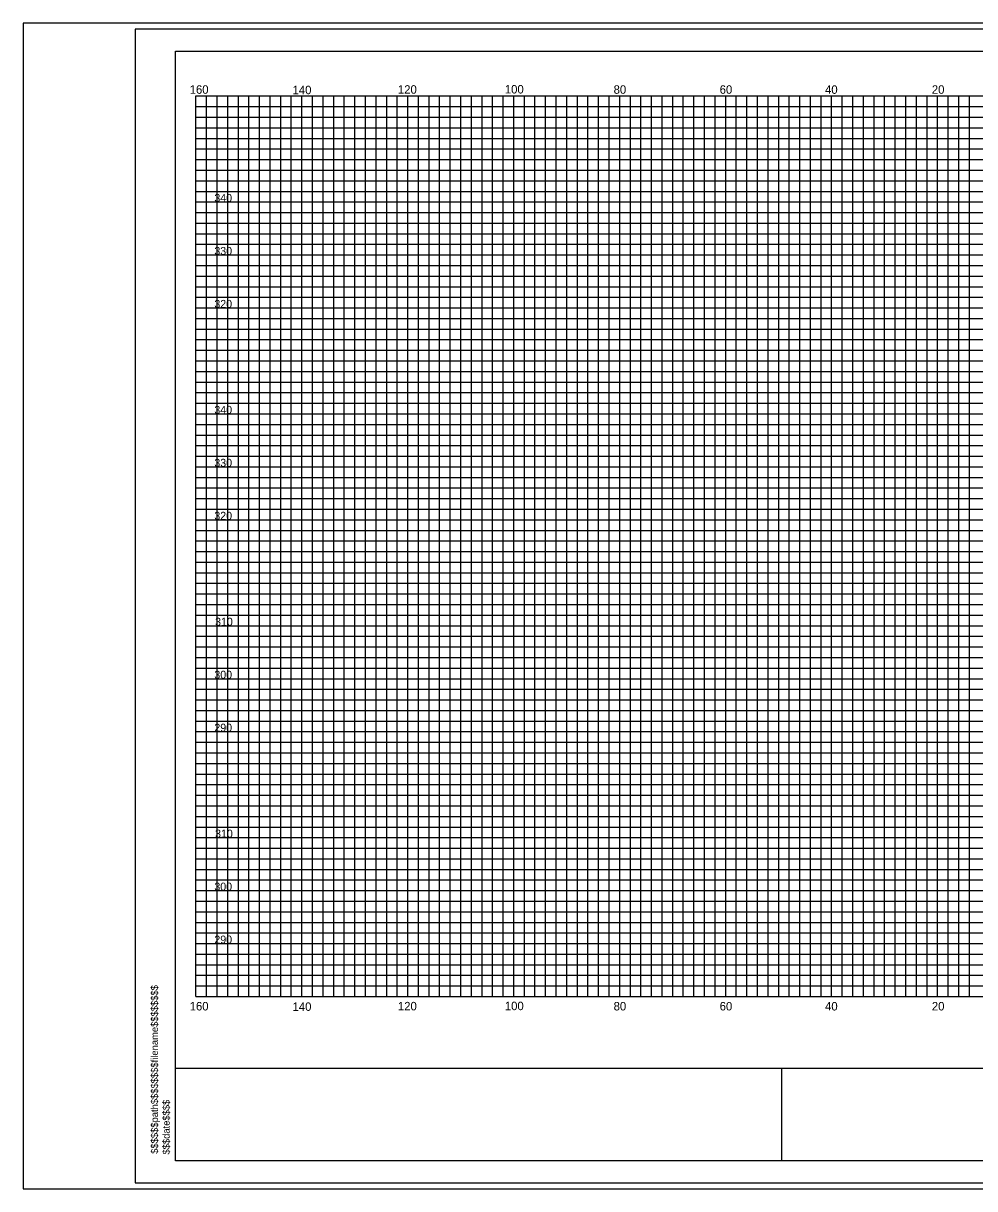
# Model space of a CAD drawing. Extents: x 967 to 1326, y 964 to 3704.
# Drawn here: x 967.4 to 1147, y 2923.7 to 3143.7 of the extents above; entities that cross this region are included whole.
import ezdxf

# ---------------------------------------------------------------- set-up
doc = ezdxf.new("R2010")
doc.units = 0
for name, color, linetype in [('Default', 7, 'Continuous'), ('RD_SHT_Bndy', 7, 'Continuous'), ('RD_SHT_IplotShp', 7, 'Continuous'), ('RD_SHT_MjGrid', 7, 'Continuous'), ('RD_SHT_MnGrid', 7, 'Continuous'), ('RD_SHT_TX', 7, 'Continuous'), ('RD_XS_TX_Station', 7, 'Continuous')]:
    doc.layers.add(name, color=color, linetype=linetype)

msp = doc.modelspace()

# ---------------------------------------------------------------- linework, layer by layer
at = {"layer": 'RD_SHT_Bndy'}
for p, q in [((996.11, 2928.98), (996.11, 3138.46)), ((996.11, 3138.46), (1323.89, 3138.46)), ((996.11, 2946.49), (1323.89, 2946.49)), ((1110.59, 2928.98), (1110.59, 2946.56)), ((1323.89, 2928.98), (996.11, 2928.98))]:
    msp.add_line(p, q, dxfattribs=at)
at = {"layer": 'RD_SHT_IplotShp'}
for points in [[(967.41, 2923.72), (1326.28, 2923.72), (1326.28, 3143.72), (967.41, 3143.72)], [(988.52, 2924.84), (1326.28, 2924.84), (1326.28, 3142.6), (988.52, 3142.6)]]:
    msp.add_lwpolyline(points, close=True, dxfattribs=at)
at = {"layer": 'RD_SHT_MjGrid'}
for p, q in [((1000, 3130), (1320, 3130)), ((1000, 2960), (1000, 3130)), ((1010, 2960), (1010, 3130)), ((1020, 2960), (1020, 3130)), ((1030, 2960), (1030, 3130)), ((1040, 2960), (1040, 3130)), ((1050, 2960), (1050, 3130)), ((1060, 2960), (1060, 3130)), ((1070, 2960), (1070, 3130)), ((1080, 2960), (1080, 3130)), ((1090, 2960), (1090, 3130)), ((1100, 2960), (1100, 3130)), ((1110, 2960), (1110, 3130)), ((1120, 2960), (1120, 3130)), ((1130, 2960), (1130, 3130)), ((1140, 2960), (1140, 3130)), ((1000, 3120), (1320, 3120)), ((1000, 3110), (1320, 3110)), ((1000, 3100), (1320, 3100)), ((1000, 3090), (1320, 3090)), ((1000, 3080), (1320, 3080)), ((1000, 3070), (1320, 3070)), ((1000, 3060), (1320, 3060)), ((1000, 3050), (1320, 3050)), ((1000, 3040), (1320, 3040)), ((1000, 3030), (1320, 3030)), ((1000, 3020), (1320, 3020)), ((1000, 3010), (1320, 3010)), ((1000, 3000), (1320, 3000)), ((1000, 2990), (1320, 2990)), ((1000, 2980), (1320, 2980)), ((1000, 2970), (1320, 2970)), ((1000, 2960), (1320, 2960))]:
    msp.add_line(p, q, dxfattribs=at)
at = {"layer": 'RD_SHT_MnGrid'}
for p, q in [((1002, 2960), (1002, 3130)), ((1004, 2960), (1004, 3130)), ((1006, 2960), (1006, 3130)), ((1008, 2960), (1008, 3130)), ((1012, 2960), (1012, 3130)), ((1014, 2960), (1014, 3130)), ((1016, 2960), (1016, 3130)), ((1018, 2960), (1018, 3130)), ((1022, 2960), (1022, 3130)), ((1024, 2960), (1024, 3130)), ((1026, 2960), (1026, 3130)), ((1028, 2960), (1028, 3130)), ((1032, 2960), (1032, 3130)), ((1034, 2960), (1034, 3130)), ((1036, 2960), (1036, 3130)), ((1038, 2960), (1038, 3130)), ((1042, 2960), (1042, 3130)), ((1044, 2960), (1044, 3130)), ((1046, 2960), (1046, 3130)), ((1048, 2960), (1048, 3130)), ((1052, 2960), (1052, 3130)), ((1054, 2960), (1054, 3130)), ((1056, 2960), (1056, 3130)), ((1058, 2960), (1058, 3130)), ((1062, 2960), (1062, 3130)), ((1064, 2960), (1064, 3130)), ((1066, 2960), (1066, 3130)), ((1068, 2960), (1068, 3130)), ((1072, 2960), (1072, 3130)), ((1074, 2960), (1074, 3130)), ((1076, 2960), (1076, 3130)), ((1078, 2960), (1078, 3130)), ((1082, 2960), (1082, 3130)), ((1084, 2960), (1084, 3130)), ((1086, 2960), (1086, 3130)), ((1088, 2960), (1088, 3130)), ((1092, 2960), (1092, 3130)), ((1094, 2960), (1094, 3130)), ((1096, 2960), (1096, 3130)), ((1098, 2960), (1098, 3130)), ((1102, 2960), (1102, 3130)), ((1104, 2960), (1104, 3130)), ((1106, 2960), (1106, 3130)), ((1108, 2960), (1108, 3130)), ((1112, 2960), (1112, 3130)), ((1114, 2960), (1114, 3130)), ((1116, 2960), (1116, 3130)), ((1118, 2960), (1118, 3130)), ((1122, 2960), (1122, 3130)), ((1124, 2960), (1124, 3130)), ((1126, 2960), (1126, 3130)), ((1128, 2960), (1128, 3130)), ((1132, 2960), (1132, 3130)), ((1134, 2960), (1134, 3130)), ((1136, 2960), (1136, 3130)), ((1138, 2960), (1138, 3130)), ((1142, 2960), (1142, 3130)), ((1144, 2960), (1144, 3130)), ((1146, 2960), (1146, 3130)), ((1000, 3128), (1320, 3128)), ((1000, 3126), (1320, 3126)), ((1000, 3124), (1320, 3124)), ((1000, 3122), (1320, 3122)), ((1000, 3118), (1320, 3118)), ((1000, 3116), (1320, 3116)), ((1000, 3114), (1320, 3114)), ((1000, 3112), (1320, 3112)), ((1000, 3108), (1320, 3108)), ((1000, 3106), (1320, 3106)), ((1000, 3104), (1320, 3104)), ((1000, 3102), (1320, 3102)), ((1000, 3098), (1320, 3098)), ((1000, 3096), (1320, 3096)), ((1000, 3094), (1320, 3094)), ((1000, 3092), (1320, 3092)), ((1000, 3088), (1320, 3088)), ((1000, 3086), (1320, 3086)), ((1000, 3084), (1320, 3084)), ((1000, 3082), (1320, 3082)), ((1000, 3078), (1320, 3078)), ((1000, 3076), (1320, 3076)), ((1000, 3074), (1320, 3074)), ((1000, 3072), (1320, 3072)), ((1000, 3068), (1320, 3068)), ((1000, 3066), (1320, 3066)), ((1000, 3064), (1320, 3064)), ((1000, 3062), (1320, 3062)), ((1000, 3058), (1320, 3058)), ((1000, 3056), (1320, 3056)), ((1000, 3054), (1320, 3054)), ((1000, 3052), (1320, 3052)), ((1000, 3048), (1320, 3048)), ((1000, 3046), (1320, 3046)), ((1000, 3044), (1320, 3044)), ((1000, 3042), (1320, 3042)), ((1000, 3038), (1320, 3038)), ((1000, 3036), (1320, 3036)), ((1000, 3034), (1320, 3034)), ((1000, 3032), (1320, 3032)), ((1000, 3028), (1320, 3028)), ((1000, 3026), (1320, 3026)), ((1000, 3024), (1320, 3024)), ((1000, 3022), (1320, 3022)), ((1000, 3018), (1320, 3018)), ((1000, 3016), (1320, 3016)), ((1000, 3014), (1320, 3014)), ((1000, 3012), (1320, 3012)), ((1000, 3008), (1320, 3008)), ((1000, 3006), (1320, 3006)), ((1000, 3004), (1320, 3004)), ((1000, 3002), (1320, 3002)), ((1000, 2998), (1320, 2998)), ((1000, 2996), (1320, 2996)), ((1000, 2994), (1320, 2994)), ((1000, 2992), (1320, 2992)), ((1000, 2988), (1320, 2988)), ((1000, 2986), (1320, 2986)), ((1000, 2984), (1320, 2984)), ((1000, 2982), (1320, 2982)), ((1000, 2978), (1320, 2978)), ((1000, 2976), (1320, 2976)), ((1000, 2974), (1320, 2974)), ((1000, 2972), (1320, 2972)), ((1000, 2968), (1320, 2968)), ((1000, 2966), (1320, 2966)), ((1000, 2964), (1320, 2964)), ((1000, 2962), (1320, 2962))]:
    msp.add_line(p, q, dxfattribs=at)
at = {"layer": 'RD_XS_TX_Station'}
msp.add_lwpolyline([(967.41, 2923.72), (1326.28, 2923.72), (1326.28, 3143.72), (967.41, 3143.72)], close=True, dxfattribs=at)

# ---------------------------------------------------------------- texts
at = {"layer": 'Default'}
for s, p in [('340', (1003.47, 3110)), ('330', (1003.47, 3100)), ('320', (1003.47, 3090)), ('340', (1003.47, 3070)), ('330', (1003.47, 3060)), ('320', (1003.47, 3050)), ('310', (1003.61, 3030)), ('300', (1003.47, 3020)), ('290', (1003.47, 3010)), ('310', (1003.61, 2990)), ('300', (1003.47, 2980)), ('290', (1003.47, 2970))]:
    msp.add_text(s, height=1.5, dxfattribs=at).set_placement(p)
for s, p in [('$$$$$$path$$$$$$$$filename$$$$$$$$', (992.83, 2930.31)), ('$$$date$$$$', (995.04, 2930.17))]:
    msp.add_text(s, height=1.3258, rotation=90, dxfattribs=at).set_placement(p)
at = {"layer": 'RD_SHT_TX'}
for s, p in [('160', (998.81, 3130.42)), ('140', (1018.23, 3130.34)), ('120', (1038.12, 3130.43)), ('100', (1058.3, 3130.47)), ('80', (1078.84, 3130.42)), ('60', (1098.86, 3130.42)), ('40', (1118.75, 3130.41)), ('20', (1138.91, 3130.42)), ('120', (1038.12, 2957.38)), ('100', (1058.3, 2957.42)), ('160', (998.81, 2957.37)), ('140', (1018.23, 2957.29)), ('80', (1078.84, 2957.37)), ('60', (1098.86, 2957.37)), ('40', (1118.75, 2957.36)), ('20', (1138.91, 2957.37))]:
    msp.add_text(s, height=1.6, dxfattribs=at).set_placement(p)

doc.saveas('drawing.dxf')
